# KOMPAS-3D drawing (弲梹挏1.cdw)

Views: Вид 1, Вид 2, Вид 3, Вид 4, Вид 5
Referenced files in C:\Users\Администратор\Desktop\: Чертеж11.cdw
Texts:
  Крановая тележка
  Шайба 10Л ГОСТ 6402-70
  Шайба C 10.37 ГОСТ 10450-78
  Гайка М16-6H ГОСТ 5915-70
  Шайба 16Л ГОСТ 6402-70
  Гайка М12x1,5-6H (S18) ГОСТ 5915-70
  Шайба 12Л ГОСТ 6402-70
  Гайка М16x1,5-6H ГОСТ 5915-70
  Болт М14x1,5-6gx16 (S21) ГОСТ 7798-70
  Гайка М10-6H (S16) ГОСТ 5915-70
  Гайка М8x1-6H ГОСТ 5915-70
  Шайба 8Л ГОСТ 6402-70
  Гайка М22x1,5-6H ГОСТ 5915-70
  Шайба 22Л ГОСТ 6402-70
  Шпонка 25x22x70 ГОСТ 10748-79
  Шайба 20Л ГОСТ 6402-70
  Шпонка 28x25x110 ГОСТ 10748-79
  СONTINUOUS_RGB_0_0_0_THICK_0.6
  СONTINUOUS_RGB_0_0_0_THICK_0.2
  СONTINUOUS_RGB_0_0_0_THICK_0.18
  невидимая_RGB_0_0_0_SC_1_THICK_0.18
  ACAD_ISO10W100_RGB_0_0_0_SC_0.25_THICK_0.35
  POLYLINE_STYLE_0.18_RGB_0_0_0
  ACAD_ISO10W100_RGB_0_0_0_SC_1_THICK_0.35
  ACAD_ISO03W100_RGB_0_0_0_SC_0.5_THICK_0.35
  ACAD_ISO10W100_RGB_0_0_0_SC_0.3_THICK_0.35
  K5LT_BASIC_RGB_0_0_0_THICK_0.6
  POLYLINE_STYLE_0.60_RGB_0_0_0
  K5LT_AXLED_RGB_0_0_0_SC_1_THICK_0.35
  Стили документа
  Винт В.М 10-6g x 40 ГОСТ 17473-80
  Винт обычный
  Винт
  ГОСТ
  Шайба 10 Л ГОСТ 6402-70
  Шайба пружинная
  Шайба
  Шайба C  10.37 ГОСТ 10450-78
  .Ти9
  АД1 ГОСТ 4784-97
  Болт М10-6g x 65 (S16) ГОСТ 7798-70
  Болт
  Крепежное изделие ГОСТ
  Гайка
  Болт М10-6g x 55 (S16) ГОСТ 7798-70
  Болт М12 x 1,5-6g x 90 (S18) ГОСТ 7798-70
  Шайба 12 Л ГОСТ 6402-70
  Болт М16 x 1,5-6g x 90 ГОСТ 7798-70
  Шайба 16 Л ГОСТ 6402-70
  Болт М24-6g x 95 ГОСТ 7798-70
  Шайба 24 Л ГОСТ 6402-70
  Шайба C  24.37 ГОСТ 10450-78
  Гайка М24-6H ГОСТ 5915-70
  Болт М16-6g x 50 ГОСТ 7798-70
  Подшипник 1317 ГОСТ 28428-90
  Подшипник
  Болт М16-6g x 90 ГОСТ 7798-70
  Болт М16 x 1,5-6g x 95 ГОСТ 7798-70
  Болт М10-6g x 22 (S16) ГОСТ 7798-70
  Болт М6-6g x 30 ГОСТ 7798-70
  Болт М10 x 1,25-6g x 20 (S16) ГОСТ 7798-70
  Манжета 1.1-115 x140-4 ГОСТ 8752-79
  Манжета
  Болт М20 x 1,5-6g x 35 ГОСТ 7798-70
  Шайба 20 Л ГОСТ 6402-70
  Болт М10-6g x 70 (S16) ГОСТ 7798-70
  Болт М8 x 1-6g x 50 ГОСТ 7798-70
  Шайба 8 Л ГОСТ 6402-70
  Болт М12 x 1,5-6g x 30 (S18) ГОСТ 7798-70
  Шпонка 70 x 65 x 180 ГОСТ 10748-79
  Шпонка
  Подшипник 3518 ГОСТ 5721-75
  Манжета 1.1-110 x135-2 ГОСТ 8752-79
  Болт М16 x 1,5-6g x 30 ГОСТ 7798-70
  Болт М24-6g x 45 ГОСТ 7798-70
  Болт М20-6g x 30 ГОСТ 7798-70
  Болт М48-6g x 65 ГОСТ 7798-70
  Болт М24-6g x 32 ГОСТ 7798-70
  Болт М48 x 3-6g x 65 ГОСТ 7796-70
  Болт М16 x 1,5-6g x 60 ГОСТ 7798-70
  Болт М22 x 1,5-6g x 85 ГОСТ 7798-70
  Шайба 22 Л ГОСТ 6402-70
  Болт М10-6g x 30 (S16) ГОСТ 7798-70
  Шпонка 22 x 20 x 110 ГОСТ 10748-79
  Шпонка 28 x 25 x 110 ГОСТ 10748-79
  Шпонка 25 x 22 x 70 ГОСТ 10748-79
  Лит-Масса-Масштаб
  Материал-Предприятие
  Title Specification
  Body Specification ( left align )
  Body Specificaton ( centered )
  Поз.
  Кол.
  Приме-
  чание
  Таблица спецификации
  ГОСТ 7798-70
  М14x1,5-6gx16 (S21)
  ГОСТ 10748-79
  Обозначение стандарта
  Типоразмер
  Савченко В.В.
  Грачев А.А.
  СПбГПУ
  гр.33221/2
Dimensions and other numbers on the sheet: 123; 385; 2646; 249; 375; 150; 1649; 285; 434; 360; 170; 400; 160; 90; 1356; 1488; 1709; 386; 200; 500; 100; 610; 65; 85; 180; 640; 95; 115; 24,19; 20; 748; 600; 1740; 1; -6g; 80; 2; 65Г; 029; 70; 3; 78; 4; 6; 58; 40Х; 019; 7; 10; 11; 12; 13; 14; 15; 19; 21; 24; 26; 28; 29; 5; 84; 17; 30; 36; 39; 41; 42; 44; 140; 45; 46; 47; 50; 51; 52; 54; 57; 79; 18; 59; 135; 60; 61; 66; 67; 68; 72; 81; 82; 28x25x110; 25x22x70; 1:10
